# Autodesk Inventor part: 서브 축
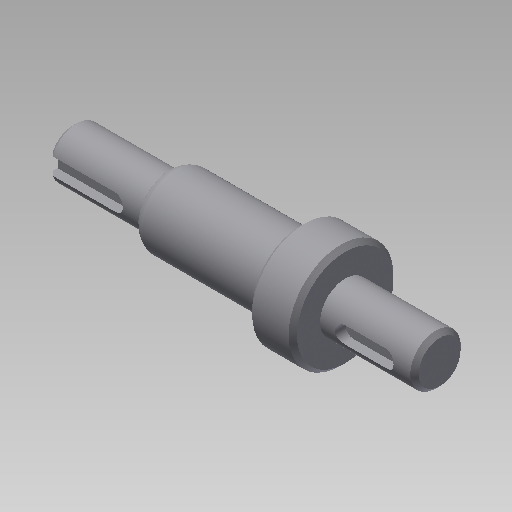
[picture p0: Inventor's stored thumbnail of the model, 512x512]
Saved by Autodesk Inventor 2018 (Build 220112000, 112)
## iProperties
Created: 2016-04
Part Number: 서브 축
Document SubType Name: Modeling
Designer: mdu
Density: 1 g/cm^3
Mass: 19.9624 g
Surface Area: 57.7178 cm^2
Volume: 19.9624 cm^3
Material: 강철, 연강
Appearance: 금속-강(스테인리스, 브러시됨)
Author: mdu
Revision Number: 1
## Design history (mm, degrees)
sketch "스케치1"
  geometry: L1 (-16.331, 0)-(-103.831, 0); L2 (-16.331, 0)-(-16.331, -6); L3 (-16.331, -6)-(-38.831, -6); L4 (-38.831, -12.5)-(-46.5, -12.5); L5 (-46.5, -8.5)-(-79.013, -8.5); L6 (-103.831, -6)-(-103.831, 0); L7 (-46.5, -8.5)-(-46.5, -12.5); L8 (-38.831, -6)-(-38.831, -12.5); L9 (-46.5, 12.249)-(-46.5, -12.249) reference; L10 (-38.831, -17)-(-38.831, 17) reference; L11 (-103.831, -6)-(-80.831, -6); L12 (-80.831, -6)-(-80.831, -7.45); L13 (-80.831, -7.45)-(-79.013, -8.5); 2 further points
  constraints: 23 end point, 6 perpendicular, 2 collinear, 2 parallel, 1 horizontal, 1 midpoint, 1 point on line
  dimensions: "d1" = 12 diameter of L3 L1; "d2" = 25 diameter of L4 L1; "d3" = 17 diameter of L5 L1; "d18" = 22.5 distance of L2.end L3.end; "d20" = 65 distance between parallel lines of L6 L8; "d21" = 7.66872 distance of L4.start L4.end (derived); "d28" = 12 diameter of L11 L1; "d29" = 23 distance of L6.start L11.end; "d30" = 14.9 diameter of L12.end L1; "d32" = 30 deg angle of L5 L13
revolve "회전1" sketch "스케치1" stored, may be unused: angle "d5" = 90 deg
chamfer "모따기1" distance "d6" = 1; stored, may be unused: second distance "d7" = 2, angle "d8" = 45 deg
node "작업 평면1"
sketch "스케치2"
  geometry: L1 (11.25, 5)-(11.25, -5) reference; L2 (-5.75, -2)-(4.25, -2); L3 (4.25, 2)-(-5.75, 2); A1 r 2 centre (4.25, 0) between (4.25, -2) and (4.25, 2); A2 r 2 centre (-5.75, 0) between (-5.75, 2) and (-5.75, -2); 2 further points
  constraints: 4 end point, 4 point on circle, 4 tangent, 2 centre point, 1 horizontal alignment, 1 midpoint, 1 parallel, 1 perpendicular
  dimensions: "d9" = 4 distance between parallel lines of L2 L3; "d10" = 14 dimension on A1 A2; "d11" = 5 distance edge to line of A1 L1
extrude "돌출1" cut sketch "스케치2" distance "d12" = 2.5; taper "d13" = 0 deg
node "작업 평면2"
sketch "스케치3"
  geometry: L1 (-103.831, -5)-(-103.831, 5) reference; L2 (-103.831, 2)-(-87.831, 2); L3 (-87.831, -2)-(-103.831, -2); A1 r 2 centre (-87.831, 0) between (-87.831, -2) and (-87.831, 2); 2 further points
  constraints: 4 end point, 2 perpendicular, 2 point on circle, 2 point on line, 2 tangent, 1 centre point, 1 horizontal alignment, 1 midpoint
  dimensions: "d14" = 4 distance between parallel lines of L3 L2; "d15" = 18 dimension on A1 L1
extrude "돌출2" cut sketch "스케치3" distance "d16" = 2.5; taper "d17" = 0 deg
sketch "스케치4"
  geometry: C1 r 12.5 at (0, 0) reference; 1 further point
extrude "돌출3" join sketch "스케치4" distance "d22" = 3; taper "d23" = 0 deg
chamfer "모따기2" distance "d24" = 1; stored, may be unused: second distance "d25" = 2, angle "d26" = 45 deg
fillet "모깎기1" dims "d34" = 1
fillet "모깎기2" dims "d35" = 2
node "솔리드1"
node "참조4"
node "참조5"
other parameters: "d33" = 6
